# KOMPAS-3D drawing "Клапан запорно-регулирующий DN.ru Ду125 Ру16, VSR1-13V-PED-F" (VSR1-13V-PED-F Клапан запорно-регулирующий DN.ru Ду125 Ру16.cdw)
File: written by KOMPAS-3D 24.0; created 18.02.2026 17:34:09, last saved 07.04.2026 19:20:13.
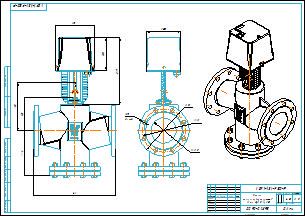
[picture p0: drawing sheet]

Document properties: Автор: R2D2; Форматы листов документа: A2; Полное имя файла: VSR1-13V-PED-F Клапан запорно-регулирующий DN.ru Ду125 Ру16.m3d; Масса: 40.6; Наименование: Клапан запорно-регулирующий DN.ru Ду125 Ру16; Количество листов документа: 1; Примечание: D090-02895

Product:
- Part/product: Клапан запорно-регулирующий DN.ru Ду125 Ру16  | designation VSR1-13V-PED-F
    Масса: 40.6
    Раздел спецификации: Прочие изделия
    Примечание: D090-02895

Views: Вид 1, Спереди
Referenced files in E:\Работа\Зайцев\Солянка\VSR1-13V-PED-F Клапан запорно-регулирующий DN.ru\DN15\DN15 Kv0.16\: VSR1-13V-PED-F Клапан запорно-регулирующий DN.ru Ду15 Ру16.m3d
Referenced files in E:\Работа\Зайцев\Солянка\VSR1-13V-PED-F Клапан запорно-регулирующий DN.ru\DN125\: VSR1-13V-PED-F Клапан запорно-регулирующий DN.ru Ду125 Ру16.m3d
Referenced files in E:\Работа\Зайцев\Для компаса\: чертеж DN.ru А3.cdt
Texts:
  Линейный размер
  VSR1-13V-PED-F
  чертеж DN.ru А3.cdt
  Клапан
  запорно-регулирующий
  DN.ru Ду125 Ру16
  Клапан запорно-регулирующий DN.ru Ду125 Ру16
  VSR1-13V-PED-F Клапан запорно-регулирующий DN.ru Ду125 Ру16
Dimensions and other numbers on the sheet: 0; 3; 2; 4; 400; 220; 160; 235; 190; 327; 158; 1:2,5; 1; 40,6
